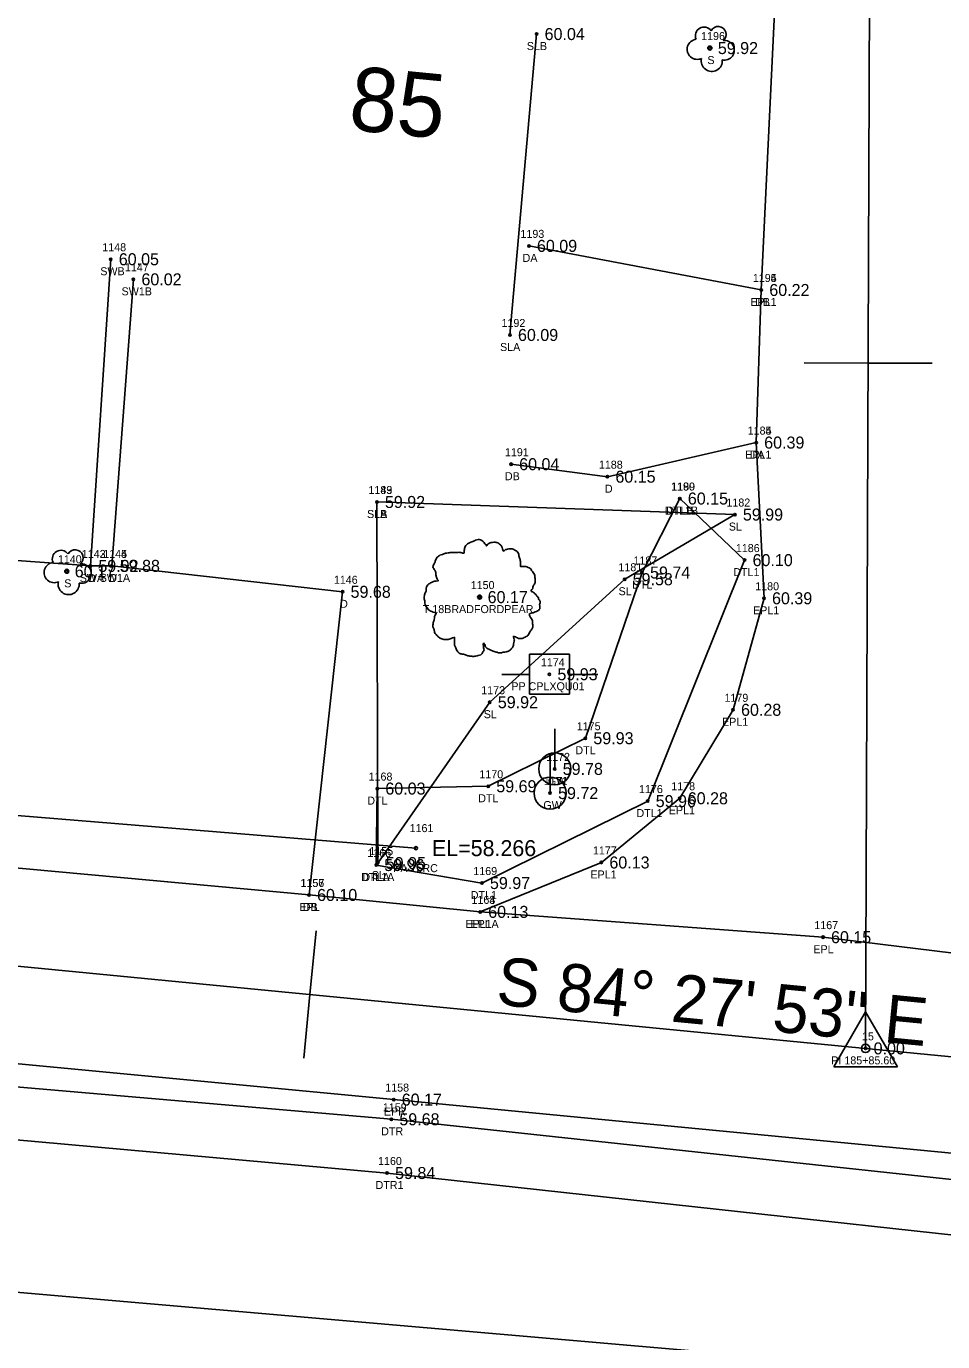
# Model space of a CAD drawing. Extents: x 2420113 to 2422887, y 845323 to 846653.
# Drawn here: x 2420854.4 to 2420968.9, y 845663.2 to 845827.5 of the extents above; entities that cross this region are included whole.
import ezdxf

# ---------------------------------------------------------------- set-up
doc = ezdxf.new("R2010")
doc.units = 0
for name, color, linetype in [('RD_EX_Conc', 7, 'Continuous'), ('RD_EX_Conc_txCode', 7, 'Continuous'), ('RD_EX_DR_Pipe', 7, 'Continuous'), ('RD_EX_DR_Pipe_txCode', 7, 'Continuous'), ('RD_EX_Driveway', 7, 'Continuous'), ('RD_EX_Driveway_txCode', 7, 'Continuous'), ('RD_EX_H2O', 7, 'Continuous'), ('RD_EX_H2O_txCode', 7, 'Continuous'), ('RD_EX_Road', 7, 'Continuous'), ('RD_EX_Road_txCode', 7, 'Continuous'), ('RD_EX_TX_Conc_ELEV', 7, 'Continuous'), ('RD_EX_TX_Driveway_ELEV', 7, 'Continuous'), ('RD_EX_TX_H2O_ELEV', 7, 'Continuous'), ('RD_EX_TX_Road_ELEV', 7, 'Continuous'), ('RD_EX_TX_UT_ELEV', 7, 'Continuous'), ('RD_EX_TX_VEG_ELEV', 7, 'Continuous'), ('RD_EX_UT', 7, 'Continuous'), ('RD_EX_UT_txCode', 7, 'Continuous'), ('RD_EX_VEG', 7, 'Continuous'), ('RD_EX_VEG_txCode', 7, 'Continuous'), ('RD_HC_Cl', 7, 'Continuous'), ('RD_HC_Data', 7, 'Continuous'), ('RD_HC_Data_Tic', 7, 'Continuous'), ('RD_HC_Survey_ELEV', 7, 'Continuous'), ('RD_HC_TX_Sta50', 7, 'Continuous'), ('RD_HC_txCode', 7, 'Continuous'), ('RD_SMD_Locator', 7, 'Continuous'), ('RD_TX_Pipe_ElevEX', 7, 'Continuous')]:
    doc.layers.add(name, color=color, linetype=linetype)

msp = doc.modelspace()

# ---------------------------------------------------------------- linework, layer by layer
at = {"layer": 'RD_EX_Conc'}
for p, q in [((2420862.38, 845760.08), (2420864.93, 845798.39)), ((2420865.05, 845760.09), (2420867.76, 845795.88))]:
    msp.add_line(p, q, dxfattribs=at)
at = {"layer": 'RD_EX_DR_Pipe'}
msp.add_line((2420903.06, 845724.83), (2420795.76, 845733.58), dxfattribs=at)
at = {"layer": 'RD_EX_Driveway'}
msp.add_line((2420917.17, 845800.06), (2420946.2, 845794.55), dxfattribs=at)
for points in [[(2420945.56, 845775.49), (2420926.97, 845771.23), (2420914.95, 845772.79)], [(2420809.42, 845763.93), (2420862.38, 845760.08), (2420865.05, 845760.09), (2420893.89, 845756.85), (2420889.7, 845718.98)]]:
    msp.add_lwpolyline(points, dxfattribs=at)
at = {"layer": 'RD_EX_H2O'}
for points in [[(2420898.09, 845722.72), (2420898.23, 845732.27), (2420912.09, 845732.56), (2420924.22, 845738.56), (2420931.3, 845759.26), (2420936.02, 845768.5)], [(2420898.09, 845722.72), (2420911.3, 845720.47), (2420932.01, 845730.71), (2420944.11, 845760.81), (2420936.02, 845768.5)], [(2420681.02, 845707.72), (2420749.24, 845704.74), (2420794.5, 845700.07), (2420899.98, 845690.96), (2421017.54, 845678.31), (2421112.89, 845668.07), (2421174.6, 845666.39), (2421234.64, 845664.08), (2421293.38, 845665.28), (2421351.67, 845667.88), (2421422.34, 845677.35), (2421426.88, 845673.47), (2421424.22, 845667.22)], [(2420681.1, 845702.44), (2420748.92, 845698.41), (2420794.23, 845693.69), (2420899.45, 845684.25), (2421017.43, 845671.31), (2421111.87, 845660.39), (2421174.2, 845656.63), (2421235.06, 845654.38), (2421294.9, 845653.67), (2421353.19, 845655.89), (2421424.22, 845667.22)]]:
    msp.add_lwpolyline(points, dxfattribs=at)
at = {"layer": 'RD_EX_Road'}
for points in [[(2420911.08, 845716.87), (2420926.22, 845723.04), (2420936.01, 845731.06), (2420942.67, 845742.11), (2420946.54, 845756.04), (2420945.56, 845775.49), (2420946.2, 845794.55), (2420948.14, 845835.31), (2420948.56, 845856.76), (2420948.65, 845897.5), (2420947.59, 845964.03), (2420948.31, 845983.28), (2420948.75, 845998.25), (2420949.7, 846105.56), (2420949.53, 846120.86), (2420949.28, 846141.3), (2420949.41, 846199.43)], [(2420388.28, 845680.39), (2420441.29, 845692.04), (2420492.62, 845700.7), (2420553.92, 845707.41), (2420607.69, 845710.85), (2420682.38, 845711.26), (2420749.44, 845707.27), (2420795.12, 845703.44), (2420900.28, 845693.42), (2421017.17, 845682.19), (2421113.9, 845672.97), (2421174.87, 845668.16), (2421234.59, 845666.13), (2421293, 845667.25), (2421351.24, 845671.5), (2421419.82, 845681.17), (2421463.19, 845688.63), (2421558.82, 845713.18), (2421614.57, 845730.45), (2421670.73, 845751.42), (2421735.61, 845780.5), (2421750.75, 845787.87), (2421744.67, 845798.22), (2421739.21, 845808.11)], [(2420376.35, 845701.93), (2420403.68, 845709.11), (2420436.45, 845715.41), (2420465.85, 845720.8), (2420487.58, 845724.76), (2420551.29, 845731.53), (2420607.05, 845734.89), (2420658.72, 845735.59), (2420682.86, 845735.47), (2420736.67, 845732.56), (2420795.4, 845727.65), (2420889.7, 845718.98), (2420911.08, 845716.87), (2420953.91, 845713.71), (2420998.34, 845708.25), (2421018.47, 845706.55), (2421116.02, 845696.98), (2421176.98, 845692), (2421235.85, 845690.14), (2421292.32, 845691.44), (2421350.22, 845695.49), (2421412.35, 845704.28)]]:
    msp.add_lwpolyline(points, dxfattribs=at)
at = {"layer": 'RD_EX_UT'}
for p, q in [((2420922.22, 845749.06), (2420917.22, 845749.06)), ((2420917.22, 845749.06), (2420917.22, 845744.06)), ((2420922.22, 845744.06), (2420922.22, 845749.06)), ((2420913.79, 845746.5), (2420917.26, 845746.5)), ((2420922.15, 845746.5), (2420925.79, 845746.5)), ((2420917.22, 845744.06), (2420922.22, 845744.06)), ((2420920.39, 845734.73), (2420920.39, 845739.73)), ((2420919.81, 845731.71), (2420919.81, 845736.71))]:
    msp.add_line(p, q, dxfattribs=at)
for centre in [(2420920.39, 845734.73), (2420919.81, 845731.71)]:
    msp.add_circle(centre, 2, dxfattribs=at)
at = {"layer": 'RD_EX_VEG'}
msp.add_line((2420914.8, 845788.93), (2420918.13, 845826.52), dxfattribs=at)
for points in [[(2420898.18, 845768.07), (2420898.29, 845722.96), (2420912.28, 845743.06), (2420929.13, 845758.42), (2420942.9, 845766.5), (2420898.18, 845768.07)], [(2420391.44, 845659.63), (2420497.12, 845682.87), (2420554.96, 845697.51), (2420665.26, 845702.88), (2420735.64, 845697.65), (2420790.66, 845674.79), (2421018.22, 845655.05), (2421176.12, 845636.22), (2421296.76, 845636.57), (2421411.61, 845653.11), (2421415.24, 845569.55)]]:
    msp.add_lwpolyline(points, dxfattribs=at)
for centre, radius in [((2420939.77, 845824.77), 0.25), ((2420859.43, 845759.41), 0.25), ((2420911.01, 845756.19), 0.25), ((2420910.99, 845756.17), 0.0001)]:
    msp.add_circle(centre, radius, dxfattribs=at)
for centre, radius, start, end in [((2420939.04, 845826.32), 1.08, 34.9763, 204.756), ((2420940.81, 845826.47), 0.995, 308.7626, 152.0467), ((2420938.2, 845824.61), 1.26, 96.4518, 294.734), ((2420941.6, 845824.49), 1.22, 256.5667, 98.1046), ((2420940.01, 845823.17), 1.32, 166.8827, 5.7589), ((2420858.7, 845760.96), 1.08, 34.9763, 204.756), ((2420860.47, 845761.11), 0.995, 308.7626, 152.0467), ((2420857.86, 845759.25), 1.26, 96.4518, 294.734), ((2420861.26, 845759.13), 1.22, 256.5667, 98.1046), ((2420859.67, 845757.81), 1.32, 166.8827, 5.7589)]:
    msp.add_arc(centre, radius, start, end, dxfattribs=at)
for points in [[(2420911.14, 845763.35), (2420910.84, 845763.38), (2420910.51, 845763.28), (2420910.26, 845763.18), (2420910.04, 845763.1), (2420909.81, 845763), (2420909.51, 845762.83), (2420909.29, 845762.63), (2420909.16, 845762.38), (2420909.11, 845762.15), (2420909.06, 845761.88), (2420909.06, 845761.71), (2420908.94, 845761.68), (2420908.79, 845761.71), (2420908.54, 845761.78), (2420908.29, 845761.78), (2420908.04, 845761.78), (2420907.69, 845761.76), (2420907.34, 845761.76), (2420907.06, 845761.71), (2420906.74, 845761.66), (2420906.36, 845761.53), (2420906.02, 845761.41), (2420905.72, 845761.16), (2420905.47, 845760.68), (2420905.34, 845760.33), (2420905.19, 845760.08), (2420905.34, 845759.63), (2420905.52, 845759.28), (2420905.54, 845759.08), (2420905.62, 845758.66), (2420905.72, 845758.43), (2420905.84, 845758.23), (2420905.77, 845758.21), (2420905.39, 845758.16), (2420905.09, 845758.06), (2420904.67, 845757.83), (2420904.44, 845757.61), (2420904.34, 845757.28), (2420904.32, 845756.93), (2420904.22, 845756.73), (2420904.14, 845756.46), (2420904.12, 845756.38), (2420904.07, 845756.06), (2420904.17, 845755.61), (2420904.19, 845755.26), (2420904.32, 845755.03), (2420904.47, 845754.86), (2420904.64, 845754.61), (2420905.04, 845754.38), (2420905.37, 845754.28), (2420905.57, 845754.26), (2420905.39, 845753.76), (2420905.34, 845753.41), (2420905.22, 845753.01), (2420905.22, 845752.93), (2420905.17, 845752.46), (2420905.32, 845752.13), (2420905.39, 845751.76), (2420905.57, 845751.53), (2420905.84, 845751.23), (2420906.16, 845751.01), (2420906.66, 845750.88), (2420907.06, 845750.91), (2420907.64, 845751.08), (2420907.89, 845751.16), (2420907.86, 845750.98), (2420907.89, 845750.61), (2420907.89, 845750.19), (2420908.04, 845749.86), (2420908.14, 845749.59), (2420908.29, 845749.34), (2420908.61, 845749.11), (2420909.01, 845749.04), (2420909.44, 845748.89), (2420909.89, 845748.81), (2420910.39, 845748.79), (2420910.99, 845748.94), (2420911.26, 845749.06), (2420911.36, 845749.24), (2420911.56, 845749.61), (2420911.51, 845749.84), (2420911.54, 845750.44), (2420911.64, 845750.26), (2420911.81, 845749.91), (2420912.31, 845749.61), (2420912.71, 845749.44), (2420913.19, 845749.29), (2420913.49, 845749.21), (2420913.96, 845749.29), (2420914.34, 845749.36), (2420914.71, 845749.49), (2420915.01, 845749.76), (2420915.19, 845750.04), (2420915.24, 845750.31), (2420915.31, 845750.68), (2420915.36, 845750.86)], [(2420915.36, 845750.86), (2420915.29, 845751.03), (2420915.24, 845751.28), (2420915.31, 845751.26), (2420915.49, 845751.21), (2420915.76, 845751.08), (2420915.99, 845751.01), (2420916.31, 845751.03), (2420916.59, 845751.13), (2420917.04, 845751.41), (2420917.31, 845751.88), (2420917.58, 845752.28), (2420917.66, 845752.61), (2420917.61, 845752.83), (2420917.58, 845753.33), (2420917.39, 845753.58), (2420917.34, 845753.71), (2420917.24, 845754.11), (2420917.31, 845754.16), (2420917.58, 845754.21), (2420917.96, 845754.33), (2420918.23, 845754.46), (2420918.46, 845754.63), (2420918.53, 845754.86), (2420918.51, 845755.26), (2420918.56, 845755.66), (2420918.48, 845755.81), (2420918.38, 845755.96), (2420918.31, 845756.16), (2420918.16, 845756.31), (2420918.06, 845756.46), (2420917.96, 845756.56), (2420917.83, 845756.71), (2420917.66, 845756.83), (2420917.51, 845756.88), (2420917.46, 845757.03), (2420917.61, 845757.23), (2420917.66, 845757.33), (2420917.68, 845757.56), (2420917.91, 845757.91), (2420917.96, 845758.31), (2420917.91, 845758.73), (2420917.86, 845759.01), (2420917.71, 845759.28), (2420917.51, 845759.53), (2420917.39, 845759.71), (2420917.21, 845759.83), (2420916.89, 845759.96), (2420916.64, 845760.01), (2420916.29, 845760.01), (2420916.09, 845760.06), (2420916.11, 845760.11), (2420916.11, 845760.26), (2420916.11, 845760.53), (2420916.04, 845760.98), (2420915.89, 845761.48), (2420915.89, 845761.51), (2420915.79, 845761.76), (2420915.56, 845761.95), (2420915.39, 845762.05), (2420915.19, 845762.18), (2420914.94, 845762.2), (2420914.64, 845762.2), (2420914.36, 845762.15), (2420914.16, 845762.05), (2420913.99, 845761.93), (2420913.91, 845762.08), (2420913.81, 845762.38), (2420913.76, 845762.53), (2420913.61, 845762.7), (2420913.39, 845762.9), (2420912.94, 845763.03), (2420912.31, 845762.95), (2420912.01, 845762.75), (2420911.86, 845762.58), (2420911.81, 845762.7), (2420911.61, 845762.9), (2420911.51, 845763.08), (2420911.34, 845763.2), (2420911.19, 845763.3), (2420911.09, 845763.35)]]:
    msp.add_spline(points, degree=3, dxfattribs=at)
at = {"layer": 'RD_HC_Cl'}
for p, q in [((2420961.04, 846199.81), (2420959.23, 845699.82)), ((2420759.62, 845719.16), (2421125.21, 845683.73))]:
    msp.add_line(p, q, dxfattribs=at)
at = {"layer": 'RD_HC_Data'}
for p, q in [((2420955.26, 845697.52), (2420959.23, 845704.4)), ((2420959.23, 845704.4), (2420963.2, 845697.52)), ((2420955.26, 845697.52), (2420963.2, 845697.52))]:
    msp.add_line(p, q, dxfattribs=at)
msp.add_circle((2420959.23, 845699.82), 0.529, dxfattribs=at)
at = {"layer": 'RD_HC_Data_Tic'}
for p, q in [((2420959.54, 845785.41), (2420951.54, 845785.44)), ((2420959.54, 845785.41), (2420967.54, 845785.39)), ((2420889.81, 845706.54), (2420890.58, 845714.5)), ((2420889.81, 845706.54), (2420889.04, 845698.58))]:
    msp.add_line(p, q, dxfattribs=at)
at = {"layer": 'RD_SMD_Locator'}
for centre, radius in [((2420918.13, 845826.52), 0.15), ((2420939.77, 845824.77), 0.15), ((2420917.17, 845800.06), 0.15), ((2420864.93, 845798.39), 0.15), ((2420867.76, 845795.88), 0.15), ((2420946.2, 845794.55), 0.15), ((2420946.2, 845794.55), 0.15), ((2420914.8, 845788.93), 0.15), ((2420945.56, 845775.49), 0.15), ((2420945.56, 845775.49), 0.15), ((2420914.95, 845772.79), 0.15), ((2420926.97, 845771.23), 0.15), ((2420898.18, 845768.07), 0.15), ((2420898.18, 845768.07), 0.15), ((2420936.02, 845768.5), 0.15), ((2420936.02, 845768.5), 0.15), ((2420942.9, 845766.5), 0.15), ((2420944.11, 845760.81), 0.15), ((2420859.43, 845759.41), 0.15), ((2420862.38, 845760.08), 0.15), ((2420862.38, 845760.08), 0.15), ((2420865.05, 845760.09), 0.15), ((2420865.05, 845760.09), 0.15), ((2420931.3, 845759.26), 0.15), ((2420929.13, 845758.42), 0.15), ((2420893.89, 845756.85), 0.15), ((2420911.01, 845756.19), 0.15), ((2420946.54, 845756.04), 0.15), ((2420919.73, 845746.55), 0.15), ((2420912.28, 845743.06), 0.15), ((2420942.67, 845742.11), 0.15), ((2420924.22, 845738.56), 0.15), ((2420920.39, 845734.73), 0.15), ((2420912.09, 845732.56), 0.15), ((2420898.23, 845732.27), 0.15), ((2420919.81, 845731.71), 0.15), ((2420936.01, 845731.06), 0.15), ((2420932.01, 845730.71), 0.15), ((2420903.06, 845724.83), 0.2), ((2420898.09, 845722.72), 0.15), ((2420898.09, 845722.72), 0.15), ((2420898.29, 845722.96), 0.15), ((2420926.22, 845723.04), 0.15), ((2420911.3, 845720.47), 0.15), ((2420889.7, 845718.98), 0.15), ((2420889.7, 845718.98), 0.15), ((2420911.08, 845716.87), 0.15), ((2420911.08, 845716.87), 0.15), ((2420953.91, 845713.71), 0.15), ((2420959.23, 845699.82), 0.15), ((2420900.28, 845693.42), 0.15), ((2420899.98, 845690.96), 0.15), ((2420899.45, 845684.25), 0.15)]:
    msp.add_circle(centre, radius, dxfattribs=at)

# ---------------------------------------------------------------- texts
at = {"layer": 'RD_EX_Conc_txCode'}
for s, p in [('1148', (2420863.87, 845799.39)), ('SWB', (2420863.62, 845796.39)), ('1147', (2420866.7, 845796.88)), ('SW1B', (2420866.28, 845793.88)), ('1143', (2420861.31, 845761.08)), ('1144', (2420863.99, 845761.09)), ('SWA', (2420861.05, 845758.08)), ('SW1A', (2420863.55, 845758.09))]:
    msp.add_text(s, height=1, dxfattribs=at).set_placement(p)
at = {"layer": 'RD_EX_DR_Pipe_txCode'}
for s, p in [('1161', (2420902.26, 845726.83)), ('PA 15RC', (2420900.22, 845721.83))]:
    msp.add_text(s, height=1, dxfattribs=at).set_placement(p)
at = {"layer": 'RD_EX_Driveway_txCode'}
for s, p in [('1193', (2420916.11, 845801.06)), ('DA', (2420916.38, 845798.06)), ('1194', (2420945.14, 845795.55)), ('DB', (2420945.42, 845792.55)), ('1185', (2420944.5, 845776.49)), ('1191', (2420914.17, 845773.79)), ('DA', (2420944.76, 845773.49)), ('1188', (2420925.91, 845772.23)), ('DB', (2420914.17, 845770.79)), ('D', (2420926.66, 845769.23)), ('1142', (2420861.31, 845761.08)), ('1145', (2420863.99, 845761.09)), ('D', (2420862.07, 845758.08)), ('D', (2420864.74, 845758.09)), ('1146', (2420892.8, 845757.85)), ('D', (2420893.58, 845754.85)), ('1156', (2420888.62, 845719.98)), ('DB', (2420888.92, 845716.98))]:
    msp.add_text(s, height=1, dxfattribs=at).set_placement(p)
at = {"layer": 'RD_EX_H2O_txCode'}
for s, p in [('1190', (2420934.92, 845769.5)), ('1189', (2420934.95, 845769.5)), ('DTL1B', (2420934.14, 845766.5)), ('DTLB', (2420934.3, 845766.5)), ('1186', (2420943.02, 845761.81)), ('1187', (2420930.23, 845760.26)), ('DTL1', (2420942.7, 845758.81)), ('DTL', (2420930.05, 845757.26)), ('1175', (2420923.15, 845739.56)), ('DTL', (2420922.97, 845736.56)), ('1170', (2420910.98, 845733.56)), ('1168', (2420897.14, 845733.27)), ('1176', (2420930.92, 845731.71)), ('DTL', (2420896.98, 845730.27)), ('DTL', (2420910.84, 845730.56)), ('DTL1', (2420930.6, 845728.71)), ('1166', (2420896.98, 845723.72)), ('1165', (2420897, 845723.72)), ('DTL1A', (2420896.19, 845720.72)), ('DTLA', (2420896.36, 845720.72)), ('1169', (2420910.22, 845721.47)), ('DTL1', (2420909.9, 845718.47)), ('1159', (2420898.92, 845691.96)), ('DTR', (2420898.71, 845688.96)), ('1160', (2420898.32, 845685.25)), ('DTR1', (2420898.01, 845682.25))]:
    msp.add_text(s, height=1, dxfattribs=at).set_placement(p)
at = {"layer": 'RD_EX_Road_txCode'}
for s, p in [('1195', (2420945.14, 845795.55)), ('EPL1', (2420944.83, 845792.55)), ('1184', (2420944.5, 845776.49)), ('EPL1', (2420944.19, 845773.49)), ('1180', (2420945.44, 845757.04)), ('EPL1', (2420945.17, 845754.04)), ('1179', (2420941.6, 845743.11)), ('EPL1', (2420941.3, 845740.11)), ('1178', (2420934.95, 845732.06)), ('EPL1', (2420934.64, 845729.06)), ('1177', (2420925.16, 845724.04)), ('EPL1', (2420924.85, 845721.04)), ('1157', (2420888.64, 845719.98)), ('EPL', (2420888.5, 845716.98)), ('1163', (2420909.99, 845717.87)), ('1164', (2420909.99, 845717.87)), ('EPL1A', (2420909.22, 845714.87)), ('EPL', (2420909.87, 845714.87)), ('1167', (2420952.82, 845714.71)), ('EPL', (2420952.7, 845711.71)), ('1158', (2420899.22, 845694.42)), ('EPR', (2420899.05, 845691.42))]:
    msp.add_text(s, height=1, dxfattribs=at).set_placement(p)
at = {"layer": 'RD_EX_TX_Conc_ELEV'}
for s, p in [('60.05', (2420865.93, 845797.64)), ('60.02', (2420868.76, 845795.13)), ('59.92', (2420863.38, 845759.33)), ('59.88', (2420866.05, 845759.34))]:
    msp.add_text(s, height=1.5, dxfattribs=at).set_placement(p)
at = {"layer": 'RD_EX_TX_Driveway_ELEV'}
for s, p in [('60.09', (2420918.17, 845799.31)), ('60.22', (2420947.2, 845793.8)), ('60.39', (2420946.56, 845774.74)), ('60.04', (2420915.95, 845772.04)), ('60.15', (2420927.97, 845770.48)), ('59.92', (2420863.38, 845759.33)), ('59.88', (2420866.05, 845759.34)), ('59.68', (2420894.89, 845756.1)), ('60.10', (2420890.7, 845718.23))]:
    msp.add_text(s, height=1.5, dxfattribs=at).set_placement(p)
at = {"layer": 'RD_EX_TX_H2O_ELEV'}
for s, p in [('60.15', (2420937.02, 845767.75)), ('60.15', (2420937.02, 845767.75)), ('60.10', (2420945.11, 845760.06)), ('59.74', (2420932.3, 845758.51)), ('59.93', (2420925.22, 845737.81)), ('60.03', (2420899.23, 845731.52)), ('59.69', (2420913.09, 845731.81)), ('59.96', (2420933.01, 845729.96)), ('59.96', (2420899.09, 845721.97)), ('59.96', (2420899.09, 845721.97)), ('59.97', (2420912.3, 845719.72)), ('59.68', (2420900.98, 845690.21)), ('59.84', (2420900.45, 845683.5))]:
    msp.add_text(s, height=1.5, dxfattribs=at).set_placement(p)
at = {"layer": 'RD_EX_TX_Road_ELEV'}
for s, p in [('60.22', (2420947.2, 845793.8)), ('60.39', (2420946.56, 845774.74)), ('60.39', (2420947.54, 845755.29)), ('60.28', (2420943.67, 845741.36)), ('60.28', (2420937.01, 845730.31)), ('60.13', (2420927.22, 845722.29)), ('60.10', (2420890.7, 845718.23)), ('60.13', (2420912.08, 845716.12)), ('60.13', (2420912.08, 845716.12)), ('60.15', (2420954.91, 845712.96)), ('60.17', (2420901.28, 845692.67))]:
    msp.add_text(s, height=1.5, dxfattribs=at).set_placement(p)
at = {"layer": 'RD_EX_TX_UT_ELEV'}
for s, p in [('59.78', (2420921.39, 845733.98)), ('59.72', (2420920.81, 845730.96))]:
    msp.add_text(s, height=1.5, dxfattribs=at).set_placement(p)
at = {"layer": 'RD_EX_TX_VEG_ELEV'}
for s, p in [('60.04', (2420919.13, 845825.77)), ('59.92', (2420940.77, 845824.02)), ('60.09', (2420915.8, 845788.18)), ('59.92', (2420899.18, 845767.32)), ('59.92', (2420899.18, 845767.32)), ('59.99', (2420943.9, 845765.75)), ('60.17', (2420860.43, 845758.66)), ('59.58', (2420930.13, 845757.67)), ('60.17', (2420912.01, 845755.44)), ('59.92', (2420913.28, 845742.31)), ('59.95', (2420899.29, 845722.21))]:
    msp.add_text(s, height=1.5, dxfattribs=at).set_placement(p)
at = {"layer": 'RD_EX_UT_txCode'}
for s, p in [('1174', (2420918.66, 845747.55)), ('PP CPLXQU01', (2420914.97, 845744.55)), ('1172', (2420919.32, 845735.73)), ('1171', (2420919.03, 845732.71)), ('GW', (2420919.54, 845732.73)), ('GW', (2420918.97, 845729.71))]:
    msp.add_text(s, height=1, dxfattribs=at).set_placement(p)
at = {"layer": 'RD_EX_VEG_txCode'}
for s, p in [('1196', (2420938.68, 845825.77)), ('SLB', (2420916.91, 845824.52)), ('S', (2420939.46, 845822.77)), ('1192', (2420913.74, 845789.93)), ('SLA', (2420913.56, 845786.93)), ('1149', (2420897.12, 845769.07)), ('1183', (2420897.12, 845769.07)), ('1182', (2420941.84, 845767.5)), ('SLA', (2420896.94, 845766.07)), ('SLB', (2420896.95, 845766.07)), ('SL', (2420942.14, 845764.5)), ('1140', (2420858.32, 845760.41)), ('1181', (2420928.35, 845759.42)), ('S', (2420859.12, 845757.41)), ('1150', (2420909.9, 845757.19)), ('SL', (2420928.37, 845756.42)), ('T 18BRADFORDPEAR', (2420903.91, 845754.19)), ('1173', (2420911.21, 845744.06)), ('SL', (2420911.52, 845741.06)), ('1155', (2420897.23, 845723.96)), ('SL', (2420897.54, 845720.96))]:
    msp.add_text(s, height=1, dxfattribs=at).set_placement(p)
at = {"layer": 'RD_HC_Data'}
msp.add_text('S 84%%d 27\' 53" E', height=6, rotation=354.4648, dxfattribs=at).set_placement((2420912.96, 845705.3))
at = {"layer": 'RD_HC_Survey_ELEV'}
for s, p in [('59.93', (2420920.73, 845745.8)), ('0.00', (2420960.23, 845699.07))]:
    msp.add_text(s, height=1.5, dxfattribs=at).set_placement(p)
at = {"layer": 'RD_HC_TX_Sta50'}
msp.add_text('85', height=8, rotation=354.4648, dxfattribs=at).set_placement((2420894.5, 845814.59))
at = {"layer": 'RD_HC_txCode'}
for s, p in [('15', (2420958.78, 845700.82)), ('PI 185+85.60', (2420954.94, 845697.82))]:
    msp.add_text(s, height=1, dxfattribs=at).set_placement(p)
at = {"layer": 'RD_TX_Pipe_ElevEX'}
msp.add_text('EL=58.266', height=2, dxfattribs=at).set_placement((2420905.06, 845723.83))

doc.saveas('drawing.dxf')
